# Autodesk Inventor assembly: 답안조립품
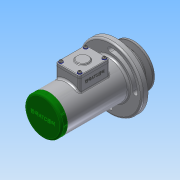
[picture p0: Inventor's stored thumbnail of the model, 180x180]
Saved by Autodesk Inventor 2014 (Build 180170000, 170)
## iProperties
Created: 2017-05
Part Number: 답안조립품
Document SubType Name: Assembly
Designer: user
Author: user
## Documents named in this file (20)
- C:\Users\user\Desktop\470508V1015\답안조립품.iam
- C:\Users\user\Desktop\470508V1015\1-본체.ipt
- C:\Users\user\Desktop\470508V1015\사이드 커버.ipt
- 사이드 커버.ipt
- C:\Users\user\Desktop\470508V1015\축.ipt
- C:\Users\user\Desktop\470508V1015\부시1.ipt
- C:\Users\user\Desktop\470508V1015\멈춤링 15 x 1.ipt
- C:\Users\user\Desktop\470508V1015\베어링 15 x 35 x 11.ipt
- C:\Users\user\Desktop\470508V1015\멈춤링 35x1.6.ipt
- C:\Users\user\Desktop\470508V1015\부시2.ipt
- C:\Users\user\Desktop\470508V1015\와셔 10x21.ipt
- C:\Users\user\Desktop\470508V1015\너트 M10.ipt
- C:\Users\user\Desktop\470508V1015\오일 실 15 25 7.ipt
- C:\Users\user\Desktop\470508V1015\키 4 x 4 x 18.ipt
- C:\Users\user\Desktop\470508V1015\V-벨트풀리.ipt
- C:\Users\user\Desktop\470508V1015\와셔 4x16.ipt
- C:\Users\user\Desktop\470508V1015\볼트 M4 x 10.ipt
- C:\Users\user\Desktop\470508V1015\탑 커버.ipt
- C:\Users\user\Desktop\470508V1015\와셔 3x6.ipt
- C:\Users\user\Desktop\470508V1015\십자볼트 M3 x 10.ipt
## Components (3 placed, 3 different names)
1. 1-본체:1 — Mate:1, Mate:2, Mate:22, Mate:28, Flush:1, Flush:2, Mate:39, Mate:40
2. V-벨트풀리:1 — Mate:33, Angle:2, Mate:34, Mate:36
3. ISO 4017 M4 x 10:1 — Mate:37, Mate:38
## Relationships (14: Mate 11, Flush 2, Angle 1)
- Mate:1: 1-본체:1
- Mate:2: 1-본체:1
- Mate:22: 1-본체:1
- Mate:28: 1-본체:1
- Flush:1: 1-본체:1
- Mate:33: V-벨트풀리:1
- Angle:2: V-벨트풀리:1
- Mate:34: V-벨트풀리:1
- Mate:36: V-벨트풀리:1
- Mate:37: ISO 4017 M4 x 10:1
- Mate:38: ISO 4017 M4 x 10:1
- Flush:2: 1-본체:1
- Mate:39: 1-본체:1
- Mate:40: 1-본체:1
